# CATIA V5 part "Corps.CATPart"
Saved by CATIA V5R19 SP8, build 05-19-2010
Part number: Corps
Publications: "Longueur_corps"
Bounding box of the stored display mesh (mm): x -2 to 115.389, y -22 to 22, z -22 to 22
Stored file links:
  E:\IAO_2010\iao\IAO_MMS_Groupe2\IAO_MMS_Groupe2\OK\nmoissenet\nmoissenet\nmoissenet\Corps.CATPart
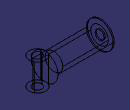
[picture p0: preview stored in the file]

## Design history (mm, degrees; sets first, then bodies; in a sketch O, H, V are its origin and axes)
Parameters
  Longueur_corps = 75 mm
Body1 (main body)
  Sketch1 on yz-plane, origin (0, 0, 0), H (0, 1, 0), V (0, 0, 1)
    circle A1 centre (0, 0) radius 22
    circle A2 centre (0, 0) radius 14.5
    radius A2 = 14.5
    radius A1 = 22
  Pad1: profile Sketch1, direction (1, 0, 0), length 75 {= Longueur_corps}
  Sketch2 on end face of Pad1, origin (75, 0, 0), H (0, 1, 0), V (0, 0, 1)
    circle A1 centre (0, 0) radius 22
    radius A1 = 22
  Pad2: profile Sketch2, direction (1, 0, 0), length 15
  Sketch3 on start face of Pad1, origin (0, 0, 0), H (0, -1, 0), V (0, 0, 1)
    circle A1 centre (0, 0) radius 22
    circle A2 centre (0, 0) radius 7.5
    radius A1 = 22
    radius A2 = 7.5
  Pad3: profile Sketch3, direction (-1, 0, 0), length 2
  Sketch4 on zx-plane, origin (0, 0, 0), H (-1, 0, 0), V (0, 0, 1)
    line L1 (-102, 22) -> (-115.5, 22)
    line L2 (-115.5, 22) -> (-115.5, -22)
    line L3 (-115.5, -22) -> (-102, -22)
    line L4 (-102, -22) -> (-102, 22)
    reference projected line E1 (-90, -22) -> (-90, 22) from edge [face of Pad2 | end face of Pad2]
    length L1 = 13.5
    length L2 = 44
    distance L1 H = 22
    distance E1 L4 = 12
    horizontal: L1 H, L3 H
    vertical: L2 V, L4 V
  Shaft1: profile Sketch4, axis Sketch4.L4, angle 360
  Sketch5 on face of Shaft1 from Sketch4.L1, origin (0, 0, 22), H (1, 0, 0), V (0, 1, 0)
    circle A1 centre (102, 0) radius 7.5
    point P1 (102, 0)
    reference projected circle E1 centre (102, 0) radius 13.5 from edge [face of Shaft1 from Sketch4.L2 | face of Shaft1 from Sketch4.L1]
    radius A1 = 7.5
    distance P1 E1 = 13.5
    coincidence: P1 H
  Pocket1: profile Sketch5, direction (0, 0, -1), through (limit type 6)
